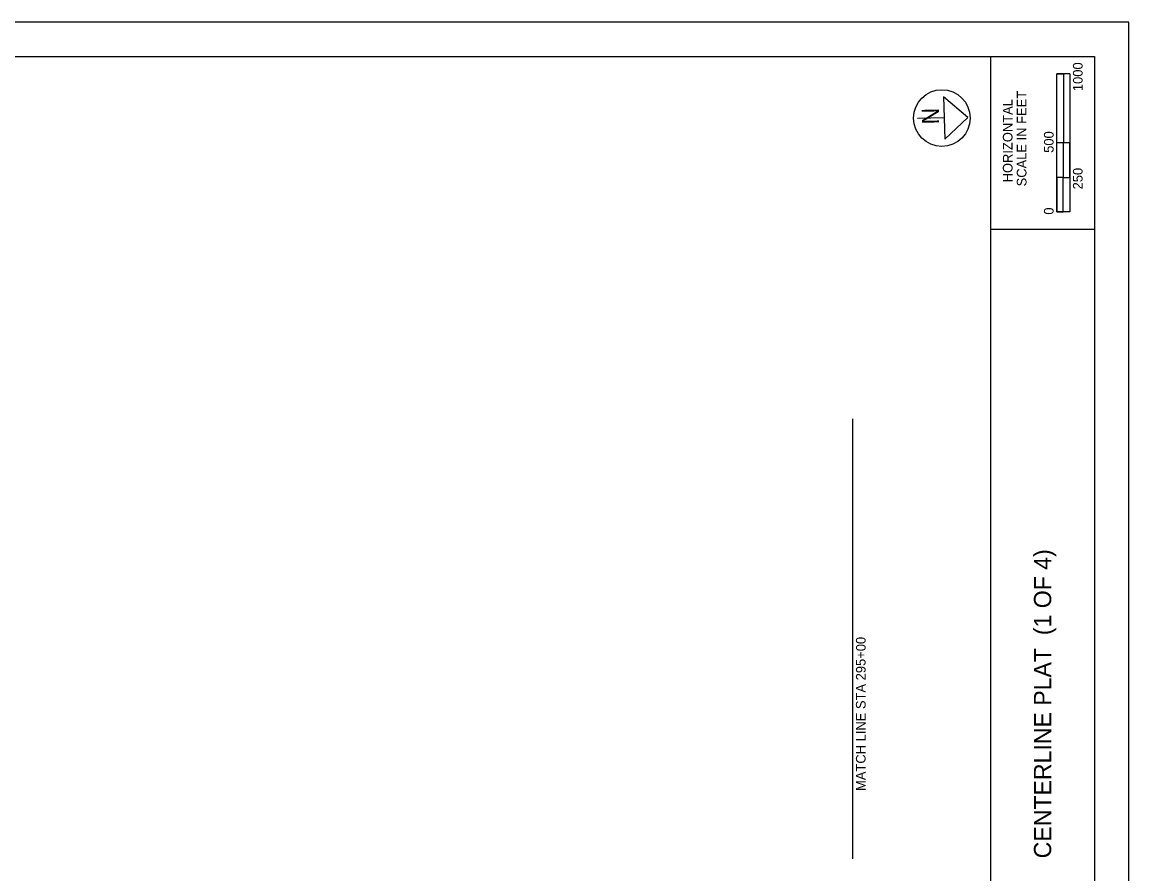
# Model space of a CAD drawing. Extents: x 0 to 34, y -0.2 to 22.
# Drawn here: x 17.97 to 34, y 9.66 to 22 of the extents above; entities that cross this region are included whole.
import ezdxf

# ---------------------------------------------------------------- set-up
doc = ezdxf.new("R2010")
doc.units = 0
for name, color, linetype in [('SH_Border', 7, 'Continuous'), ('SH_Cut_Line', 7, 'Continuous'), ('SH_Data', 7, 'Continuous'), ('SH_Masking', 7, 'Continuous'), ('SH_Text', 7, 'Continuous')]:
    doc.layers.add(name, color=color, linetype=linetype)

msp = doc.modelspace()

# ---------------------------------------------------------------- linework, layer by layer
at = {"layer": 'SH_Border'}
for p, q in [((32, 0.5), (32, 21.5)), ((32, 19), (33.5, 19))]:
    msp.add_line(p, q, dxfattribs=at)
msp.add_lwpolyline([(1.5, 21.5), (33.5, 21.5), (33.5, 0.5), (1.5, 0.5)], close=True, dxfattribs=at)
at = {"layer": 'SH_Cut_Line'}
msp.add_lwpolyline([(0, 0), (34, 0), (34, 22), (0, 22)], close=True, dxfattribs=at)
at = {"layer": 'SH_Data'}
for p, q in [((32.957, 19.25), (32.957, 21.25)), ((33.144, 21.25), (32.957, 21.25)), ((32.957, 20.25), (32.957, 21.25)), ((32.957, 21.25), (33.05, 21.25)), ((33.05, 21.25), (33.051, 21.25)), ((33.051, 21.25), (33.051, 20.25)), ((33.144, 21.25), (33.144, 19.25)), ((33.051, 20.25), (32.957, 20.25)), ((33.143, 20.25), (33.05, 20.25)), ((33.05, 20.25), (33.05, 19.75)), ((33.143, 19.75), (33.143, 20.25)), ((33.05, 19.75), (32.957, 19.75)), ((32.957, 19.75), (32.957, 19.25)), ((33.05, 19.75), (33.143, 19.75)), ((33.05, 19.25), (33.05, 19.75)), ((33.144, 19.25), (32.957, 19.25)), ((32.957, 19.25), (33.05, 19.25))]:
    msp.add_line(p, q, dxfattribs=at)
at = {"layer": 'SH_Masking'}
msp.add_circle((31.292, 20.611), 0.41, dxfattribs=at)
at = {"layer": 'SH_Text'}
for p, q in [((31.666, 20.62), (31.317, 20.92)), ((31.317, 20.92), (31.332, 20.305)), ((31.325, 20.612), (30.938, 20.603)), ((31.332, 20.305), (31.666, 20.62)), ((30, 9.883), (30, 16.253))]:
    msp.add_line(p, q, dxfattribs=at)
msp.add_circle((31.292, 20.611), 0.41, dxfattribs=at)

# ---------------------------------------------------------------- texts
at = {"layer": 'SH_Data'}
for s, height, p in [('1000', 0.14, (33.33, 21.001)), ('SCALE IN FEET', 0.14, (32.517, 19.621)), ('HORIZONTAL', 0.14, (32.315, 19.679)), ('500', 0.14, (32.91, 20.107)), ('250', 0.14, (33.33, 19.577)), ('0', 0.14, (32.91, 19.211)), ('CENTERLINE PLAT  (1 OF 4)', 0.25, (32.875, 9.888))]:
    msp.add_text(s, height=height, rotation=90, dxfattribs=at).set_placement(p)
at = {"layer": 'SH_Text'}
for s, height, rotation, p in [('N', 0.25, 271.3751, (30.997, 20.756)), ('MATCH LINE STA 295+00', 0.14, 90, (30.187, 10.864))]:
    msp.add_text(s, height=height, rotation=rotation, dxfattribs=at).set_placement(p)

doc.saveas('drawing.dxf')
